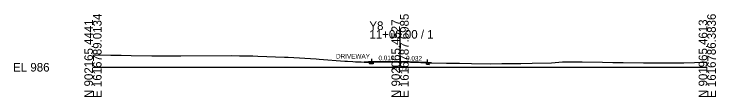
# Model space of a CAD drawing. Extents: x -26 to 1403, y -10 to 3025.
# Drawn here: x -25.7 to 202.8, y 990.3 to 1017.4 of the extents above; entities that cross this region are included whole.
import ezdxf

# ---------------------------------------------------------------- set-up
doc = ezdxf.new("R2010")
doc.units = 0
for name, color, linetype in [('Exist Cross Section Cell', 7, 'Continuous'), ('Exist XS Center Line Elevation Label', 7, 'Continuous'), ('Exist XS Ground Line', 7, 'Continuous'), ('Prop XS Dump Level', 7, 'Continuous'), ('Prop XS Earthwork Shape', 7, 'Continuous'), ('Prop XS EOT Tick Mark', 7, 'Continuous'), ('Prop XS Finish Grade', 7, 'Continuous'), ('Prop XS Finish Grade Earthwork', 7, 'Continuous'), ('Prop XS Finish Grade Pavement', 7, 'Continuous'), ('Prop XS Pvmt Edge Slope', 7, 'Continuous'), ('Prop XS SE Text', 7, 'Continuous'), ('Prop XS SS Elevation Text', 7, 'Continuous'), ('Prop XS Subgrade Earthwork', 7, 'Continuous')]:
    doc.layers.add(name, color=color, linetype=linetype)

msp = doc.modelspace()

# ---------------------------------------------------------------- linework, layer by layer
at = {"layer": 'Exist Cross Section Cell'}
for p, q in [((100, 1000), (100, 1012.15)), ((0, 1000), (100, 1000)), ((100, 1000), (200, 1000))]:
    msp.add_line(p, q, dxfattribs=at)
at = {"layer": 'Exist XS Ground Line'}
for p, q in [((0, 1004.05), (5.86, 1003.99)), ((0, 1004.05), (5.86, 1003.99)), ((5.86, 1003.99), (9.17, 1003.94)), ((5.86, 1003.99), (9.17, 1003.94)), ((9.17, 1003.94), (12.48, 1003.89)), ((9.17, 1003.94), (12.48, 1003.89)), ((12.48, 1003.89), (19.17, 1003.77)), ((12.48, 1003.89), (19.17, 1003.77)), ((19.17, 1003.77), (21.9, 1003.78)), ((19.17, 1003.77), (21.9, 1003.78)), ((21.9, 1003.78), (28.6, 1003.72)), ((21.9, 1003.78), (28.6, 1003.72)), ((28.6, 1003.72), (44.99, 1003.82)), ((28.6, 1003.72), (44.99, 1003.82)), ((44.99, 1003.82), (47.67, 1003.78)), ((44.99, 1003.82), (47.67, 1003.78)), ((47.67, 1003.78), (48.37, 1003.78)), ((47.67, 1003.78), (48.37, 1003.78)), ((48.37, 1003.78), (52.08, 1003.69)), ((48.37, 1003.78), (52.08, 1003.69)), ((52.08, 1003.69), (53.68, 1003.66)), ((52.08, 1003.69), (53.68, 1003.66)), ((53.68, 1003.66), (62.39, 1003.33)), ((53.68, 1003.66), (62.39, 1003.33)), ((62.39, 1003.33), (63.53, 1003.28)), ((62.39, 1003.33), (63.53, 1003.28)), ((63.53, 1003.28), (72.64, 1002.72)), ((63.53, 1003.28), (72.64, 1002.72)), ((72.64, 1002.72), (73.64, 1002.65)), ((72.64, 1002.72), (73.64, 1002.65)), ((73.64, 1002.65), (81.96, 1002)), ((73.64, 1002.65), (81.96, 1002)), ((81.96, 1002), (82.85, 1001.95)), ((81.96, 1002), (82.85, 1001.95)), ((82.85, 1001.95), (84.66, 1001.86)), ((82.85, 1001.95), (84.66, 1001.86)), ((84.66, 1001.86), (85.52, 1001.82)), ((84.66, 1001.86), (85.52, 1001.82)), ((85.52, 1001.82), (86.42, 1001.78)), ((85.52, 1001.82), (86.42, 1001.78)), ((86.42, 1001.78), (87.3, 1001.75)), ((86.42, 1001.78), (87.3, 1001.75)), ((87.3, 1001.75), (88.34, 1001.72)), ((87.3, 1001.75), (88.34, 1001.72)), ((88.34, 1001.72), (88.93, 1001.72)), ((88.34, 1001.72), (88.93, 1001.72)), ((88.93, 1001.72), (89.47, 1001.71)), ((88.93, 1001.72), (89.47, 1001.71)), ((89.47, 1001.71), (89.96, 1001.71)), ((89.47, 1001.71), (89.96, 1001.71)), ((89.96, 1001.71), (90.38, 1001.71)), ((89.96, 1001.71), (90.38, 1001.71)), ((90.38, 1001.71), (91.24, 1001.71)), ((90.38, 1001.71), (91.24, 1001.71)), ((91.24, 1001.71), (95.56, 1001.75)), ((91.24, 1001.71), (95.56, 1001.75)), ((95.56, 1001.75), (100.03, 1001.79)), ((95.56, 1001.75), (100.03, 1001.79)), ((100.03, 1001.79), (106.76, 1001.53)), ((100.03, 1001.79), (106.76, 1001.53)), ((106.76, 1001.53), (108.56, 1001.46)), ((106.76, 1001.53), (108.56, 1001.46)), ((108.56, 1001.46), (115.11, 1001.39)), ((108.56, 1001.46), (115.11, 1001.39)), ((115.11, 1001.39), (119.29, 1001.3)), ((115.11, 1001.39), (119.29, 1001.3)), ((119.29, 1001.3), (123.26, 1001.26)), ((119.29, 1001.3), (123.26, 1001.26)), ((123.26, 1001.26), (129.29, 1001.17)), ((123.26, 1001.26), (129.29, 1001.17)), ((129.29, 1001.17), (133.14, 1001.21)), ((129.29, 1001.17), (133.14, 1001.21)), ((133.14, 1001.21), (139.29, 1001.22)), ((133.14, 1001.21), (139.29, 1001.22)), ((139.29, 1001.22), (143.01, 1001.29)), ((139.29, 1001.22), (143.01, 1001.29)), ((143.01, 1001.29), (149.29, 1001.48)), ((143.01, 1001.29), (149.29, 1001.48)), ((149.29, 1001.48), (152.88, 1001.74)), ((149.29, 1001.48), (152.88, 1001.74)), ((152.88, 1001.74), (159.29, 1001.76)), ((152.88, 1001.74), (159.29, 1001.76)), ((159.29, 1001.76), (165.88, 1001.7)), ((159.29, 1001.76), (165.88, 1001.7)), ((165.88, 1001.7), (169.3, 1001.54)), ((165.88, 1001.7), (169.3, 1001.54)), ((169.3, 1001.54), (172.62, 1001.52)), ((169.3, 1001.54), (172.62, 1001.52)), ((172.62, 1001.52), (179.3, 1001.46)), ((172.62, 1001.52), (179.3, 1001.46)), ((179.3, 1001.46), (182.49, 1001.47)), ((179.3, 1001.46), (182.49, 1001.47)), ((182.49, 1001.47), (189.3, 1001.48)), ((182.49, 1001.47), (189.3, 1001.48)), ((189.3, 1001.48), (192.37, 1001.5)), ((189.3, 1001.48), (192.37, 1001.5)), ((192.37, 1001.5), (199.3, 1001.65)), ((192.37, 1001.5), (199.3, 1001.65)), ((199.3, 1001.65), (200, 1001.65)), ((199.3, 1001.65), (200, 1001.65))]:
    msp.add_line(p, q, dxfattribs=at)
at = {"layer": 'Prop XS Dump Level'}
for p, q in [((100, 1001.83), (90.83, 1001.74)), ((108.97, 1001.55), (100, 1001.83))]:
    msp.add_line(p, q, dxfattribs=at)
at = {"layer": 'Prop XS Earthwork Shape'}
for points in [[(89.66, 1001.73), (88.34, 1001.72), (88.93, 1001.72), (89.47, 1001.71), (89.68, 1001.71)], [(90.24, 1001.15), (89.68, 1001.71), (89.96, 1001.71), (90.38, 1001.71), (90.8, 1001.71)], [(91.24, 1001.16), (90.83, 1001.16), (90.24, 1001.15), (90.8, 1001.71), (91.24, 1001.71)], [(108.97, 1000.96), (109.58, 1000.94), (109.06, 1001.46), (108.56, 1001.46), (108.56, 1000.98)], [(108.97, 1001.55), (109.06, 1001.46), (110.26, 1001.44)]]:
    msp.add_lwpolyline(points, close=True, dxfattribs=at)
at = {"layer": 'Prop XS EOT Tick Mark'}
for p, q in [((90.83, 1001.74), (90.83, 1002.74)), ((108.97, 1001.55), (108.97, 1002.55))]:
    msp.add_line(p, q, dxfattribs=at)
at = {"layer": 'Prop XS Finish Grade'}
for p, q in [((90.83, 1001.74), (89.66, 1001.73)), ((108.97, 1001.55), (110.26, 1001.44))]:
    msp.add_line(p, q, dxfattribs=at)
at = {"layer": 'Prop XS Finish Grade Earthwork'}
msp.add_line((89.66, 1001.73), (88.34, 1001.72), dxfattribs=at)
at = {"layer": 'Prop XS Finish Grade Pavement'}
for p, q in [((90.83, 1001.74), (100, 1001.83)), ((100, 1001.83), (108.97, 1001.55))]:
    msp.add_line(p, q, dxfattribs=at)
at = {"layer": 'Prop XS Pvmt Edge Slope'}
for p, q in [((90.83, 1001.74), (90.24, 1001.15)), ((108.97, 1001.55), (109.58, 1000.94))]:
    msp.add_line(p, q, dxfattribs=at)
at = {"layer": 'Prop XS Subgrade Earthwork'}
for p, q in [((90.24, 1001.15), (89.66, 1001.73)), ((90.83, 1001.16), (90.24, 1001.15)), ((91.24, 1001.16), (90.83, 1001.16)), ((91.24, 1001.16), (91.24, 1001.71)), ((108.56, 1000.98), (108.56, 1001.46)), ((108.56, 1000.98), (108.97, 1000.96)), ((108.97, 1000.96), (109.58, 1000.94))]:
    msp.add_line(p, q, dxfattribs=at)

# ---------------------------------------------------------------- texts
at = {"layer": 'Exist Cross Section Cell'}
for s, p in [('E 1616789.0134', (2.8, 990)), ('E 1616787.6985', (102.8, 990)), ('E 1616786.3836', (202.8, 990)), ('N 902165.4441', (0, 990)), ('N 902065.4527', (100, 990)), ('N 901965.4613', (200, 990))]:
    msp.add_text(s, height=2.8, rotation=90, dxfattribs=at).set_placement(p)
for s, p in [('Y8', (90, 1012.15)), ('11+00.00 / 1', (90, 1009.35)), ('EL 986', (-26, 998.6))]:
    msp.add_text(s, height=2.8, dxfattribs=at).set_placement(p)
at = {"layer": 'Exist XS Center Line Elevation Label'}
msp.add_text('987.79', height=1.25, dxfattribs=at).set_placement((97.1, 999.17))
at = {"layer": 'Prop XS Dump Level'}
for s, height, p in [('Case1', 0.04, (87.83, 1001.49)), ('Eop', 0.3, (108.56, 1001.16)), ('Case1', 0.04, (111.97, 1001.27))]:
    msp.add_text(s, height=height, dxfattribs=at).set_placement(p)
at = {"layer": 'Prop XS SE Text'}
for s, rotation, p in [('0.010', 0.5729, (92.97, 1002.26)), ('0.032', 358.1604, (101.92, 1002.27))]:
    msp.add_text(s, height=1.5, rotation=rotation, dxfattribs=at).set_placement(p)
at = {"layer": 'Prop XS SS Elevation Text'}
msp.add_text('DRIVEWAY', height=1.5, dxfattribs=at).set_placement((79.14, 1002.85))

doc.saveas('drawing.dxf')
